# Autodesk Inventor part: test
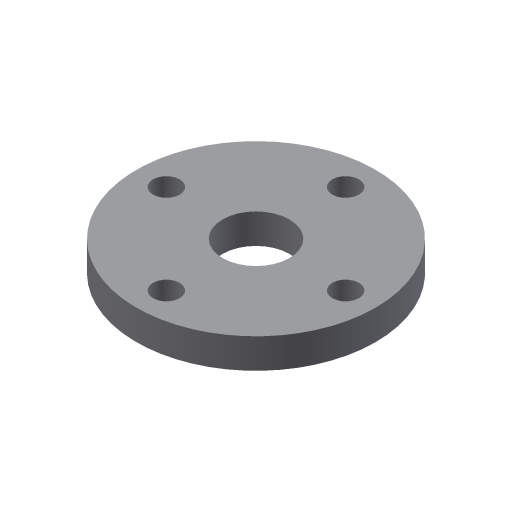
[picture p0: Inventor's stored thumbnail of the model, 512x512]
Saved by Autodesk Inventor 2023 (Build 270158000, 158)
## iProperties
Created: 2002-02
Part Number: test
Document SubType Name: Modeling
Designer: ***
Density: 1 g/cm^3
Material: Generic
Appearance: Default
Control State: 0
Master: False
Checked Out: False
Shininess: 65.0
Angle Display Precision: 2
Document Length Units: 11269
Document Angle Units: 11279
Document Time Units: 11290
Document Mass Units: 11283
Document Length Units Precision: 3
Document Angle Units Precision: 2
Density: 0.0
Volumn: 0.0
Area: 0.0
PropertySet Name: Model Information
Author: ***
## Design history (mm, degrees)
sketch "Sketch1"
  geometry: C1 r 100 at (0, 0); C2 r 28 at (0, 0)
  constraints: 2 centre point, 1 coincident
  dimensions: "d0" = 200 diameter of C1; "d1" = 56 diameter of C2
extrude "Extrusion1" new body sketch "Sketch1" stored distance "d2" = 25; taper "d3" = 0 deg
sketch "Sketch2"
  geometry: 2 further points
  dimensions: "d4" = 75 distance of point (0, 0) point (-75, 0)
hole "Hole1" sketch "Sketch2" at (-75, 0) diameter "d5" = 22.3; stored, may be unused: countersink angle "d9" = 82 deg, drill point angle "d11" = 118 deg; dims "d6" = 6, "d7" = 4, "d8" = 2, "d10" = 8
pattern_circular "Circular Pattern1" dims angle "d14" = 360 deg
body "Solid1"
